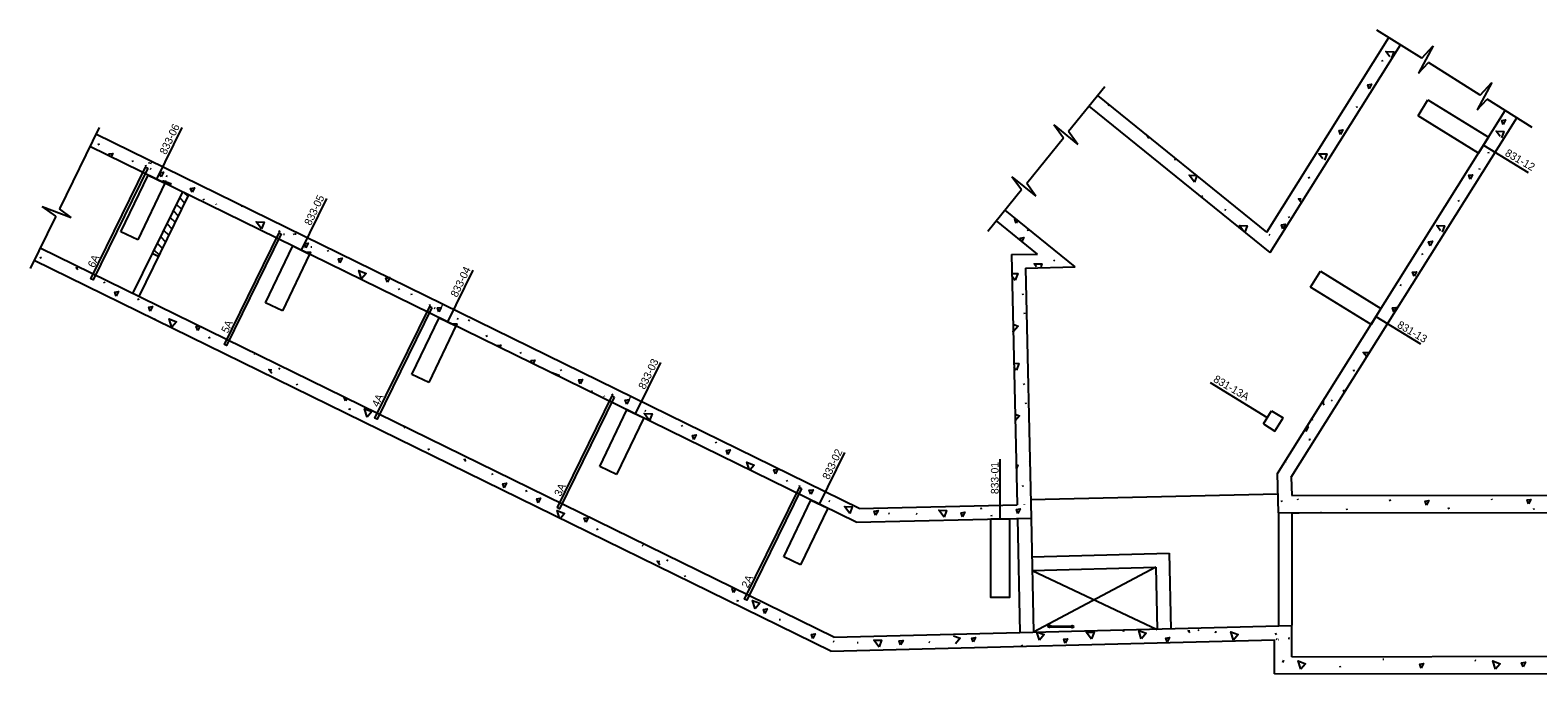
# Model space of a CAD drawing. Extents: x 9888 to 10179, y 10284 to 10316.
# Drawn here: x 9888.5 to 9961.8, y 10284.6 to 10315.9 of the extents above; entities that cross this region are included whole.
import ezdxf

# ---------------------------------------------------------------- set-up
doc = ezdxf.new("R2010")
doc.units = 0
for name, color, linetype in [('M-CELL', 7, 'Continuous'), ('M-DEMO-PATT', 7, 'Continuous'), ('M-HVAC-RETN', 7, 'Continuous'), ('M-HVAC-RETN-N', 7, 'Continuous'), ('M-HVAC-SUPP-N', 7, 'Continuous')]:
    doc.layers.add(name, color=color, linetype=linetype)

msp = doc.modelspace()

# ---------------------------------------------------------------- linework, layer by layer
at = {"layer": 'M-CELL'}
for p, q in [((9948.585, 10306.081), (9954.513, 10315.531)), ((9956.114, 10314.527), (9953.931, 10315.896)), ((9948.75, 10305.09), (9955.078, 10315.177)), ((9956.673, 10315.138), (9955.961, 10313.81)), ((9956.114, 10314.527), (9956.673, 10315.138)), ((9954.217, 10314.369), (9954.191, 10314.437)), ((9955.961, 10313.81), (9956.447, 10314.318)), ((9958.957, 10312.743), (9956.447, 10314.318)), ((9940.711, 10313.145), (9938.951, 10310.966)), ((9959.514, 10313.353), (9958.802, 10312.025)), ((9958.957, 10312.743), (9959.514, 10313.353)), ((9948.585, 10306.081), (9940.366, 10312.718)), ((9958.802, 10312.025), (9959.289, 10312.535)), ((9961.485, 10311.158), (9959.289, 10312.535)), ((9948.75, 10305.09), (9939.947, 10312.199)), ((9940.918, 10312.215), (9940.891, 10312.283)), ((9949.096, 10294.35), (9960.16, 10311.988)), ((9952.981, 10312.114), (9952.954, 10312.182)), ((9891.842, 10311.157), (9889.908, 10307.214)), ((9938.7, 10310.654), (9938.226, 10311.291)), ((9938.226, 10311.291), (9939.395, 10310.34)), ((9939.395, 10310.34), (9938.951, 10310.966)), ((9949.773, 10294.174), (9960.725, 10311.634)), ((9928.629, 10291.982), (9891.394, 10310.243)), ((9928.777, 10292.653), (9891.674, 10310.848)), ((9891.834, 10310.314), (9891.808, 10310.382)), ((9938.7, 10310.654), (9936.914, 10308.443)), ((9893.487, 10309.498), (9893.461, 10309.566)), ((9944.086, 10309.619), (9944.138, 10309.609)), ((9959.375, 10309.904), (9959.348, 10309.972)), ((9894.127, 10309.268), (9894.101, 10309.336)), ((9894.291, 10309.398), (9894.265, 10309.466)), ((9894.31, 10309.171), (9894.363, 10309.161)), ((9894.336, 10309.448), (9894.388, 10309.438)), ((9895.087, 10308.816), (9895.139, 10308.806)), ((9936.662, 10308.131), (9936.186, 10308.773)), ((9936.186, 10308.773), (9937.354, 10307.822)), ((9950.658, 10308.693), (9950.632, 10308.761)), ((9958.937, 10309.107), (9958.911, 10309.175)), ((9895.883, 10308.042), (9893.462, 10303.104)), ((9936.662, 10308.131), (9935.026, 10306.105)), ((9937.354, 10307.822), (9936.914, 10308.443)), ((9889.736, 10306.863), (9889.075, 10307.327)), ((9889.075, 10307.327), (9890.483, 10306.791)), ((9896.183, 10307.895), (9893.761, 10302.957)), ((9895.589, 10307.441), (9895.838, 10307.192)), ((9895.744, 10307.757), (9895.993, 10307.508)), ((9895.977, 10307.996), (9896.148, 10307.825)), ((9896.942, 10307.634), (9896.915, 10307.702)), ((9897.537, 10307.415), (9897.525, 10307.447)), ((9898.749, 10307.352), (9898.801, 10307.342)), ((9945.457, 10307.788), (9945.431, 10307.856)), ((9957.926, 10307.566), (9957.9, 10307.634)), ((9889.736, 10306.863), (9888.486, 10304.314)), ((9890.483, 10306.791), (9889.908, 10307.214)), ((9895.279, 10306.809), (9895.528, 10306.559)), ((9895.434, 10307.125), (9895.683, 10306.876)), ((9937.434, 10305.016), (9935.444, 10306.623)), ((9939.27, 10304.391), (9935.863, 10307.142)), ((9946.53, 10307.175), (9946.583, 10307.165)), ((9949.684, 10306.777), (9949.658, 10306.845)), ((9949.684, 10306.777), (9949.658, 10306.845)), ((9949.684, 10306.777), (9949.658, 10306.845)), ((9894.813, 10305.86), (9895.062, 10305.611)), ((9894.968, 10306.176), (9895.218, 10305.927)), ((9895.124, 10306.492), (9895.373, 10306.243)), ((9900.618, 10306.085), (9900.592, 10306.153)), ((9900.801, 10305.988), (9900.853, 10305.978)), ((9901.324, 10305.949), (9901.298, 10306.017)), ((9901.369, 10305.999), (9901.421, 10305.989)), ((9936.989, 10306.128), (9936.963, 10306.196)), ((9948.677, 10305.969), (9948.729, 10305.927)), ((9948.677, 10305.969), (9948.729, 10305.927)), ((9948.677, 10305.969), (9948.729, 10305.927)), ((9927.535, 10286.393), (9888.972, 10305.305)), ((9894.503, 10305.227), (9894.752, 10304.978)), ((9894.658, 10305.543), (9894.907, 10305.294)), ((9902.12, 10305.367), (9902.172, 10305.357)), ((9902.978, 10305.133), (9902.951, 10305.201)), ((9927.389, 10285.722), (9888.678, 10304.707)), ((9889.017, 10304.805), (9888.99, 10304.873)), ((9894.713, 10304.899), (9894.414, 10305.045)), ((9936.173, 10304.988), (9937.434, 10305.016)), ((9936.173, 10304.988), (9936.445, 10292.821)), ((9936.854, 10304.336), (9939.27, 10304.391)), ((9938.216, 10304.731), (9938.268, 10304.689)), ((9956.165, 10304.973), (9956.139, 10305.041)), ((9892.107, 10303.597), (9892.081, 10303.665)), ((9903.752, 10304.205), (9903.774, 10304.2)), ((9936.854, 10304.336), (9937.127, 10292.173)), ((9906.432, 10303.27), (9906.406, 10303.338)), ((9907.041, 10303.014), (9907.015, 10303.082)), ((9936.745, 10303.018), (9936.719, 10303.086)), ((9955.052, 10303.52), (9955.104, 10303.51)), ((9955.052, 10303.52), (9955.104, 10303.51)), ((9955.052, 10303.52), (9955.104, 10303.51)), ((9893.761, 10302.781), (9893.734, 10302.849)), ((9907.931, 10302.498), (9907.905, 10302.566)), ((9908.115, 10302.401), (9908.167, 10302.391)), ((9908.477, 10302.513), (9908.529, 10302.503)), ((9936.829, 10302.086), (9936.803, 10302.154)), ((9894.505, 10301.858), (9894.557, 10301.848)), ((9909.228, 10301.881), (9909.28, 10301.871)), ((9909.778, 10301.813), (9909.83, 10301.772)), ((9897.215, 10300.917), (9897.189, 10300.985)), ((9910.69, 10300.998), (9910.664, 10301.066)), ((9899.371, 10300.174), (9899.424, 10300.163)), ((9912.343, 10300.182), (9912.317, 10300.25)), ((9900.561, 10299.461), (9900.613, 10299.419)), ((9914.307, 10299.343), (9914.281, 10299.411)), ((9952.833, 10299.313), (9952.807, 10299.381)), ((9901.473, 10298.646), (9901.447, 10298.714)), ((9936.807, 10298.653), (9936.781, 10298.721)), ((9915.798, 10298.319), (9915.772, 10298.387)), ((9916.394, 10298.099), (9916.381, 10298.131)), ((9916.798, 10298.15), (9916.771, 10298.218)), ((9917.605, 10298.037), (9917.657, 10298.026)), ((9936.891, 10297.721), (9936.865, 10297.789)), ((9951.702, 10297.919), (9951.754, 10297.877)), ((9903.962, 10297.485), (9904.015, 10297.474)), ((9903.995, 10297.494), (9904.048, 10297.483)), ((9918.356, 10297.405), (9918.408, 10297.394)), ((9919.197, 10297.054), (9919.202, 10297.05)), ((9906.705, 10296.553), (9906.679, 10296.621)), ((9920.18, 10296.634), (9920.154, 10296.702)), ((9950.8, 10296.931), (9950.774, 10296.999)), ((9951.384, 10296.743), (9951.384, 10296.744)), ((9907.873, 10295.49), (9907.847, 10295.558)), ((9921.834, 10295.818), (9921.808, 10295.886)), ((9950.626, 10296.005), (9950.679, 10295.994)), ((9950.659, 10296.014), (9950.712, 10296.003)), ((9937.037, 10294.946), (9937.065, 10294.923)), ((9949.501, 10294.88), (9949.475, 10294.948)), ((9910.963, 10294.282), (9910.937, 10294.35)), ((9949.145, 10292.442), (9949.096, 10294.35)), ((9949.773, 10294.174), (9949.793, 10293.277)), ((9912.617, 10293.465), (9912.591, 10293.533)), ((9925.288, 10293.954), (9925.262, 10294.022)), ((9925.897, 10293.699), (9925.871, 10293.767)), ((9936.745, 10293.702), (9936.719, 10293.77)), ((9937.106, 10293.089), (9949.121, 10293.358)), ((9949.793, 10293.277), (10084.13, 10293.451)), ((9927.297, 10293.02), (9927.349, 10293.009)), ((9928.777, 10292.653), (9936.445, 10292.824)), ((9934.723, 10292.606), (9934.697, 10292.674)), ((9936.805, 10292.832), (9936.803, 10292.838)), ((9949.145, 10292.442), (10174.705, 10292.735)), ((9949.327, 10292.969), (9949.3, 10293.037)), ((9950.11, 10293.073), (9950.096, 10293.11)), ((9950.137, 10293.286), (9950.137, 10293.286)), ((9952.494, 10292.561), (9952.468, 10292.629)), ((9954.587, 10293.011), (9954.561, 10293.079)), ((9957.445, 10292.623), (9957.419, 10292.691)), ((9959.538, 10293.073), (9959.519, 10293.123)), ((9961.578, 10292.577), (9961.552, 10292.645)), ((9928.629, 10291.982), (9937.127, 10292.173)), ((9930.195, 10292.423), (9930.247, 10292.412)), ((9931.541, 10292.397), (9931.593, 10292.386)), ((9935.227, 10292.257), (9935.201, 10292.325)), ((9936.46, 10292.158), (9936.584, 10286.623)), ((9937.127, 10292.173), (9937.251, 10286.64)), ((9949.145, 10292.443), (9949.145, 10286.942)), ((9949.793, 10292.443), (9950.156, 10292.443)), ((9949.793, 10292.443), (9949.793, 10286.975)), ((9951.184, 10292.46), (9951.236, 10292.449)), ((9960.612, 10292.46), (9960.625, 10292.457)), ((9916.071, 10291.602), (9916.045, 10291.67)), ((9917.154, 10291.471), (9917.148, 10291.487)), ((9918.228, 10290.858), (9918.28, 10290.848)), ((9937.167, 10290.306), (9943.833, 10290.475)), ((9943.833, 10290.475), (9943.916, 10286.789)), ((9919.417, 10290.146), (9919.47, 10290.104)), ((9937.184, 10289.639), (9943.182, 10289.792)), ((9943.182, 10289.792), (9937.251, 10286.64)), ((9943.182, 10289.792), (9943.249, 10286.774)), ((9920.329, 10289.331), (9920.303, 10289.399)), ((9937.184, 10289.639), (9943.249, 10286.774)), ((9922.819, 10288.169), (9922.871, 10288.159)), ((9922.852, 10288.178), (9922.904, 10288.168)), ((9924.89, 10287.257), (9924.942, 10287.246)), ((9936.584, 10286.623), (9949.796, 10286.959)), ((9938.078, 10286.897), (9939.069, 10286.888)), ((9938.079, 10286.934), (9939.069, 10286.924)), ((9945.226, 10286.768), (9945.279, 10286.726)), ((9949.796, 10285.446), (9949.796, 10286.959)), ((9927.389, 10285.722), (9948.963, 10286.271)), ((9927.504, 10286.192), (9927.556, 10286.182)), ((9927.535, 10286.393), (9936.584, 10286.623)), ((9928.668, 10286.14), (9928.721, 10286.13)), ((9932.162, 10286.166), (9932.214, 10286.156)), ((9941.582, 10286.711), (9941.634, 10286.701)), ((9941.615, 10286.72), (9941.667, 10286.71)), ((9946.059, 10286.649), (9946.111, 10286.639)), ((9946.092, 10286.658), (9946.144, 10286.648)), ((9948.963, 10284.612), (9948.963, 10286.271)), ((9949.044, 10286.523), (9949.018, 10286.591)), ((9949.051, 10286.505), (9949.025, 10286.573)), ((9949.036, 10286.314), (9949.089, 10286.304)), ((9949.153, 10286.276), (9949.169, 10286.276)), ((9949.625, 10286.36), (9949.677, 10286.349)), ((9949.632, 10286.342), (9949.684, 10286.331)), ((9936.71, 10285.952), (9936.684, 10286.02)), ((9949.796, 10285.446), (10083.296, 10285.619)), ((9954.214, 10285.332), (9954.266, 10285.322)), ((9948.963, 10284.612), (10084.13, 10284.787)), ((9952.166, 10284.915), (9952.14, 10284.984)), ((9958.691, 10285.27), (9958.743, 10285.26))]:
    msp.add_line(p, q, dxfattribs=at)
for points in [[(9954.558, 10314.605), (9954.369, 10314.854), (9954.75, 10314.848), (9954.638, 10314.54)], [(9953.554, 10313.046), (9953.486, 10313.239), (9953.669, 10313.265), (9953.554, 10313.046)], [(9952.168, 10310.828), (9952.1, 10311.022), (9952.283, 10311.048), (9952.168, 10310.828)], [(9959.915, 10310.734), (9959.727, 10310.983), (9960.108, 10310.977), (9959.995, 10310.669)], [(9960.073, 10311.317), (9960.005, 10311.51), (9960.188, 10311.537), (9960.073, 10311.317)], [(9942.853, 10310.638), (9942.714, 10310.821)], [(9892.349, 10309.797), (9892.32, 10309.88), (9892.503, 10309.906), (9892.426, 10309.759)], [(9951.298, 10309.644), (9951.11, 10309.893), (9951.491, 10309.887), (9951.378, 10309.579)], [(9894.846, 10308.771), (9894.778, 10308.964), (9894.961, 10308.99), (9894.846, 10308.771)], [(9945.065, 10308.501), (9944.807, 10308.842), (9945.173, 10308.836)], [(9945.184, 10308.826), (9945.068, 10308.508)], [(9958.462, 10308.648), (9958.394, 10308.842), (9958.577, 10308.868), (9958.462, 10308.648)], [(9894.879, 10308.556), (9895.076, 10308.553), (9895.047, 10308.474)], [(9894.998, 10308.498), (9894.974, 10308.576), (9895.33, 10308.44), (9895.267, 10308.366)], [(9896.354, 10308.015), (9896.286, 10308.208), (9896.469, 10308.235), (9896.354, 10308.015)], [(9950.258, 10307.513), (9950.117, 10307.7), (9950.258, 10307.697)], [(9950.258, 10307.513), (9950.117, 10307.7), (9950.258, 10307.697)], [(9950.258, 10307.513), (9950.117, 10307.7), (9950.258, 10307.697)], [(9899.727, 10306.234), (9899.47, 10306.575), (9899.851, 10306.569), (9899.731, 10306.241)], [(9936.402, 10306.509), (9936.334, 10306.702), (9936.336, 10306.703)], [(9936.454, 10306.608), (9936.402, 10306.509)], [(9936.642, 10305.656), (9936.596, 10305.788), (9936.779, 10305.814), (9936.68, 10305.625)], [(9947.44, 10306.148), (9947.251, 10306.397), (9947.632, 10306.391), (9947.519, 10306.084)], [(9949.358, 10306.243), (9949.29, 10306.437), (9949.473, 10306.463), (9949.358, 10306.243)], [(9949.358, 10306.243), (9949.29, 10306.437), (9949.473, 10306.463), (9949.358, 10306.243)], [(9949.358, 10306.243), (9949.29, 10306.437), (9949.473, 10306.463), (9949.358, 10306.243)], [(9957.03, 10306.148), (9956.842, 10306.397), (9957.223, 10306.391), (9957.11, 10306.084)], [(9901.879, 10305.321), (9901.811, 10305.515), (9901.994, 10305.541), (9901.879, 10305.321)], [(9901.912, 10305.107), (9902.109, 10305.104), (9902.08, 10305.025)], [(9956.514, 10305.416), (9956.446, 10305.61), (9956.629, 10305.636), (9956.514, 10305.416)], [(9890.805, 10304.243), (9890.726, 10304.347), (9890.805, 10304.346)], [(9903.538, 10304.594), (9903.469, 10304.788), (9903.653, 10304.814), (9903.538, 10304.594)], [(9937.39, 10304.388), (9937.274, 10304.541), (9937.655, 10304.535), (9937.602, 10304.391)], [(9904.59, 10303.803), (9904.464, 10304.211), (9904.82, 10304.075), (9904.595, 10303.809)], [(9905.844, 10303.65), (9905.776, 10303.844), (9905.959, 10303.87), (9905.844, 10303.65)], [(9936.193, 10304.07), (9936.476, 10304.065), (9936.356, 10303.738)], [(9936.352, 10303.731), (9936.196, 10303.937)], [(9955.737, 10303.934), (9955.669, 10304.127), (9955.853, 10304.153), (9955.737, 10303.934)], [(9955.737, 10303.934), (9955.669, 10304.127), (9955.853, 10304.153), (9955.737, 10303.934)], [(9955.737, 10303.934), (9955.669, 10304.127), (9955.853, 10304.153), (9955.737, 10303.934)], [(9892.662, 10302.969), (9892.594, 10303.163), (9892.777, 10303.189), (9892.662, 10302.969)], [(9894.321, 10302.242), (9894.252, 10302.436), (9894.436, 10302.462), (9894.321, 10302.242)], [(9908.347, 10302.202), (9908.279, 10302.396), (9908.462, 10302.422), (9908.347, 10302.202)], [(9954.752, 10302.2), (9954.684, 10302.394), (9954.867, 10302.42), (9954.752, 10302.2)], [(9895.373, 10301.451), (9895.247, 10301.859), (9895.603, 10301.723), (9895.378, 10301.456)], [(9896.627, 10301.298), (9896.559, 10301.492), (9896.706, 10301.512)], [(9896.733, 10301.499), (9896.627, 10301.298)], [(9909.02, 10301.621), (9909.217, 10301.618), (9909.188, 10301.539)], [(9936.249, 10301.604), (9936.494, 10301.51), (9936.269, 10301.243)], [(9936.264, 10301.238), (9936.256, 10301.263)], [(9911.177, 10300.563), (9911.176, 10300.564), (9911.36, 10300.59), (9911.311, 10300.497)], [(9953.435, 10300.013), (9953.266, 10300.236), (9953.572, 10300.231)], [(9900.233, 10299.21), (9900.092, 10299.396), (9900.233, 10299.394)], [(9912.872, 10299.732), (9912.835, 10299.837), (9913.018, 10299.863), (9912.934, 10299.702)], [(9913.843, 10299.256), (9914.186, 10299.125), (9914.164, 10299.098)], [(9936.291, 10299.705), (9936.538, 10299.701), (9936.418, 10299.373)], [(9936.415, 10299.366), (9936.295, 10299.524)], [(9915.21, 10298.699), (9915.142, 10298.893), (9915.325, 10298.919), (9915.21, 10298.699)], [(9903.811, 10297.877), (9903.747, 10298.059)], [(9903.874, 10297.997), (9903.811, 10297.877)], [(9917.475, 10297.726), (9917.407, 10297.919), (9917.59, 10297.945), (9917.475, 10297.726)], [(9951.374, 10297.668), (9951.267, 10297.81)], [(9951.293, 10297.853), (9951.374, 10297.852)], [(9952.351, 10298.285), (9952.315, 10298.387), (9952.425, 10298.403)], [(9904.863, 10297.086), (9904.738, 10297.495), (9905.093, 10297.359), (9904.868, 10297.092)], [(9918.569, 10296.938), (9918.326, 10297.259), (9918.707, 10297.253), (9918.588, 10296.929)], [(9936.347, 10297.226), (9936.557, 10297.145), (9936.354, 10296.905)], [(9950.475, 10296.397), (9950.441, 10296.494)], [(9950.511, 10296.606), (9950.59, 10296.617), (9950.475, 10296.397)], [(9920.735, 10296.006), (9920.667, 10296.199), (9920.85, 10296.226), (9920.735, 10296.006)], [(9909.661, 10294.927), (9909.583, 10295.031), (9909.661, 10295.03)], [(9922.394, 10295.279), (9922.326, 10295.472), (9922.509, 10295.498), (9922.394, 10295.279)], [(9923.425, 10294.556), (9923.32, 10294.896), (9923.676, 10294.76), (9923.481, 10294.529)], [(9924.7, 10294.335), (9924.632, 10294.528), (9924.815, 10294.554), (9924.7, 10294.335)], [(9936.402, 10294.751), (9936.476, 10294.75), (9936.406, 10294.561)], [(9911.518, 10293.654), (9911.45, 10293.847), (9911.633, 10293.873), (9911.518, 10293.654)], [(9926.416, 10293.341), (9926.348, 10293.534), (9926.531, 10293.56), (9926.416, 10293.341)], [(9913.177, 10292.926), (9913.109, 10293.12), (9913.292, 10293.146), (9913.177, 10292.926)], [(9928.315, 10292.4), (9928.058, 10292.741), (9928.439, 10292.735), (9928.318, 10292.407)], [(9936.482, 10292.406), (9936.413, 10292.6), (9936.597, 10292.626), (9936.482, 10292.406)], [(9956.346, 10292.811), (9956.278, 10293.005), (9956.461, 10293.031), (9956.346, 10292.811)], [(9961.297, 10292.873), (9961.229, 10293.067), (9961.412, 10293.093), (9961.297, 10292.873)], [(9914.214, 10292.183), (9914.103, 10292.544), (9914.459, 10292.408), (9914.254, 10292.164)], [(9915.483, 10291.982), (9915.415, 10292.176), (9915.598, 10292.202), (9915.483, 10291.982)], [(9929.573, 10292.328), (9929.505, 10292.522), (9929.688, 10292.548), (9929.573, 10292.328)], [(9932.896, 10292.219), (9932.638, 10292.559), (9933.019, 10292.553), (9932.899, 10292.225)], [(9933.791, 10292.25), (9933.723, 10292.444), (9933.906, 10292.47), (9933.791, 10292.25)], [(9919.089, 10289.894), (9918.948, 10290.081), (9919.089, 10290.078)], [(9922.667, 10288.562), (9922.599, 10288.755), (9922.691, 10288.769)], [(9922.758, 10288.736), (9922.667, 10288.562)], [(9923.719, 10287.771), (9923.594, 10288.179), (9923.95, 10288.043), (9923.725, 10287.776)], [(9924.19, 10287.551), (9924.122, 10287.745), (9924.305, 10287.771), (9924.19, 10287.551)], [(9926.519, 10286.331), (9926.451, 10286.525), (9926.634, 10286.551), (9926.519, 10286.331)], [(9929.739, 10285.91), (9929.481, 10286.251), (9929.862, 10286.245), (9929.742, 10285.917)], [(9930.789, 10286.02), (9930.721, 10286.213), (9930.904, 10286.239), (9930.789, 10286.02)], [(9933.354, 10286.463), (9933.673, 10286.341), (9933.448, 10286.074)], [(9934.309, 10286.16), (9934.24, 10286.353), (9934.424, 10286.38), (9934.309, 10286.16)], [(9937.532, 10286.251), (9937.411, 10286.644)], [(9937.443, 10286.645), (9937.762, 10286.523), (9937.537, 10286.256)], [(9938.786, 10286.098), (9938.718, 10286.291), (9938.901, 10286.317), (9938.786, 10286.098)], [(9940.064, 10286.3), (9939.807, 10286.64), (9940.188, 10286.634), (9940.067, 10286.306)], [(9942.482, 10286.313), (9942.357, 10286.721), (9942.713, 10286.585), (9942.488, 10286.318)], [(9943.737, 10286.16), (9943.669, 10286.353), (9943.852, 10286.38), (9943.737, 10286.16)], [(9944.836, 10286.598), (9944.757, 10286.702), (9944.836, 10286.701)], [(9946.96, 10286.251), (9946.834, 10286.659), (9947.19, 10286.523), (9946.965, 10286.256)], [(9949.396, 10285.277), (9949.339, 10285.167)], [(9950.23, 10284.832), (9950.105, 10285.24), (9950.461, 10285.104), (9950.236, 10284.837)], [(9956.085, 10284.894), (9956.017, 10285.088), (9956.2, 10285.114), (9956.085, 10284.894)], [(9959.689, 10284.832), (9959.564, 10285.24), (9959.92, 10285.104), (9959.695, 10284.837)], [(9961.035, 10284.956), (9960.967, 10285.15), (9961.151, 10285.176), (9961.035, 10284.956)]]:
    msp.add_lwpolyline(points, dxfattribs=at)
for centre in [(9938.022, 10286.918), (9939.125, 10286.907)]:
    msp.add_circle(centre, 0.0591, dxfattribs=at)
at = {"layer": 'M-DEMO-PATT'}
for points in [[(9894.201, 10309.183), (9891.54, 10303.756), (9891.435, 10303.807), (9894.096, 10309.234)], [(9900.692, 10306), (9898.03, 10300.572), (9897.925, 10300.624), (9900.587, 10306.051)], [(9908.005, 10302.413), (9905.344, 10296.986), (9905.239, 10297.037), (9907.901, 10302.464)], [(9916.872, 10298.065), (9914.21, 10292.638), (9914.105, 10292.689), (9916.767, 10298.116)], [(9925.972, 10293.614), (9923.31, 10288.186), (9923.205, 10288.238), (9925.867, 10293.665)]]:
    msp.add_lwpolyline(points, close=True, dxfattribs=at)
at = {"layer": 'M-HVAC-RETN'}
for p, q in [((9895.85, 10311.161), (9894.623, 10308.66)), ((9959.114, 10310.31), (9961.277, 10308.981)), ((9902.883, 10307.712), (9901.656, 10305.21)), ((9909.991, 10304.226), (9908.764, 10301.725)), ((9953.884, 10301.983), (9956.047, 10300.654)), ((9919.119, 10299.749), (9917.892, 10297.248)), ((9945.833, 10298.765), (9948.602, 10297.063)), ((9928.06, 10295.364), (9926.833, 10292.863)), ((9935.627, 10292.139), (9935.627, 10295.04))]:
    msp.add_line(p, q, dxfattribs=at)
at = {"layer": 'M-HVAC-RETN-N'}
for p, q in [((9955.939, 10311.729), (9956.414, 10312.502)), ((9956.414, 10312.502), (9959.351, 10310.697)), ((9958.876, 10309.924), (9955.939, 10311.729)), ((9959.351, 10310.697), (9958.876, 10309.924)), ((9892.896, 10306.097), (9894.214, 10308.855)), ((9894.214, 10308.855), (9895.032, 10308.464)), ((9895.032, 10308.464), (9893.714, 10305.706)), ((9893.714, 10305.706), (9892.896, 10306.097)), ((9899.929, 10302.648), (9901.247, 10305.406)), ((9901.247, 10305.406), (9902.065, 10305.015)), ((9902.065, 10305.015), (9900.747, 10302.257)), ((9950.71, 10303.402), (9951.185, 10304.175)), ((9951.185, 10304.175), (9954.122, 10302.369)), ((9953.647, 10301.597), (9950.71, 10303.402)), ((9900.747, 10302.257), (9899.929, 10302.648)), ((9954.122, 10302.369), (9953.647, 10301.597)), ((9907.037, 10299.162), (9908.355, 10301.92)), ((9909.173, 10301.529), (9907.855, 10298.771)), ((9908.355, 10301.92), (9909.173, 10301.529)), ((9907.855, 10298.771), (9907.037, 10299.162)), ((9916.165, 10294.686), (9917.483, 10297.443)), ((9918.301, 10297.052), (9916.983, 10294.294)), ((9917.483, 10297.443), (9918.301, 10297.052)), ((9948.414, 10296.756), (9948.81, 10297.401)), ((9948.81, 10297.401), (9949.372, 10297.057)), ((9948.975, 10296.411), (9949.372, 10297.057)), ((9948.414, 10296.756), (9948.975, 10296.411)), ((9916.983, 10294.294), (9916.165, 10294.686)), ((9925.106, 10290.301), (9926.424, 10293.059)), ((9927.242, 10292.668), (9925.924, 10289.91)), ((9926.424, 10293.059), (9927.242, 10292.668)), ((9925.924, 10289.91), (9925.106, 10290.301))]:
    msp.add_line(p, q, dxfattribs=at)
msp.add_lwpolyline([(9935.174, 10292.139), (9936.081, 10292.139), (9936.081, 10288.328), (9935.174, 10288.328)], close=True, dxfattribs=at)

# ---------------------------------------------------------------- texts
at = {"layer": 'M-DEMO-PATT'}
for s, p in [('6A', (9891.599, 10304.317)), ('5A', (9898.09, 10301.134)), ('4A', (9905.403, 10297.547)), ('3A', (9914.27, 10293.199)), ('2A', (9923.369, 10288.748))]:
    msp.add_text(s, height=0.375, rotation=64.23081, dxfattribs=at).set_placement(p)
at = {"layer": 'M-HVAC-SUPP-N'}
for s, rotation, p in [('833-06', 64.23081, (9895.089, 10309.816)), ('831-12', 329.81037, (9960.123, 10309.821)), ('833-05', 64.23081, (9902.122, 10306.367)), ('833-04', 64.23081, (9909.23, 10302.881)), ('831-13', 329.81037, (9954.884, 10301.469)), ('833-03', 64.23081, (9918.358, 10298.404)), ('831-13A', 329.81037, (9945.951, 10298.829)), ('833-02', 64.23081, (9927.299, 10294.019)), ('833-01', 90, (9935.549, 10293.349))]:
    msp.add_text(s, height=0.375, rotation=rotation, dxfattribs=at).set_placement(p)

doc.saveas('drawing.dxf')
